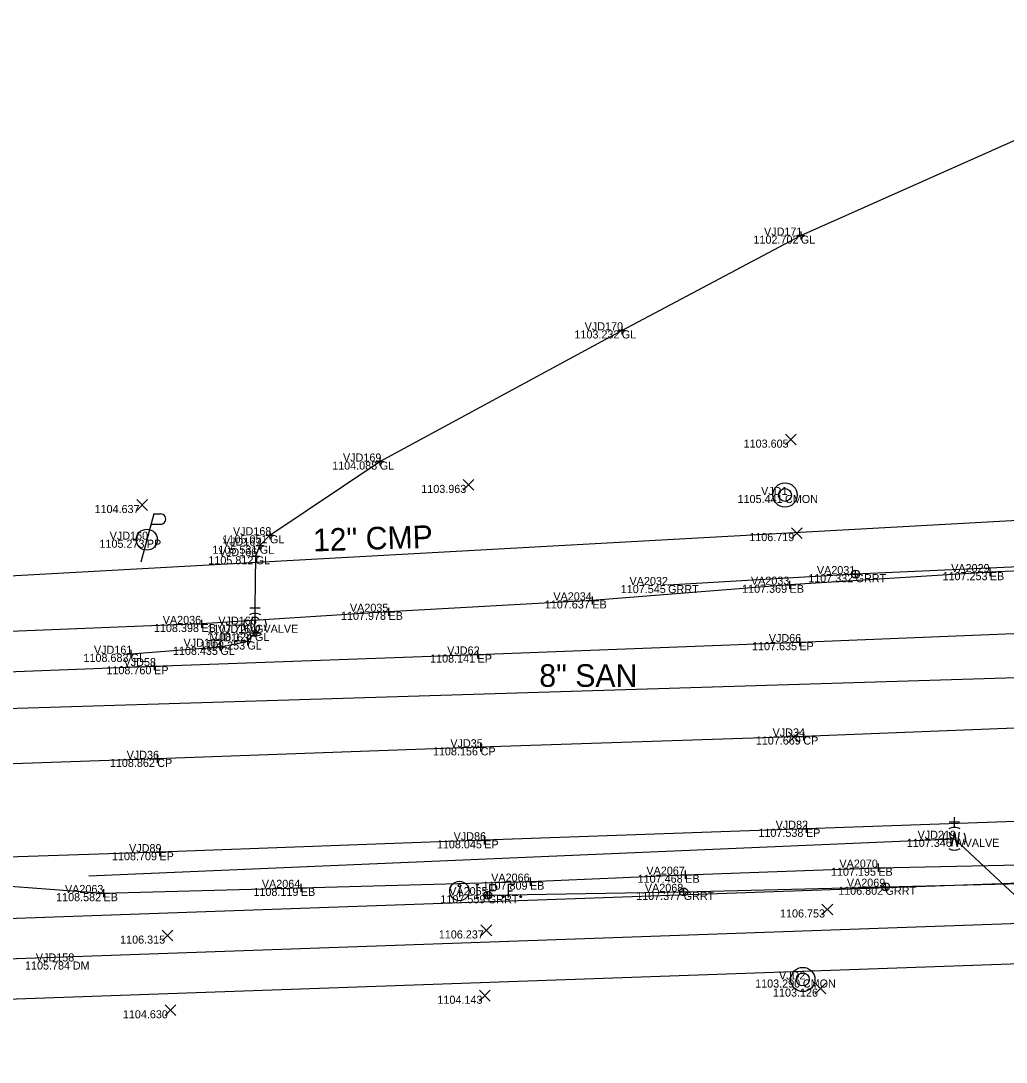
# Model space of a CAD drawing. Extents: x 1629915 to 1630675, y 484401 to 484601.
# Drawn here: x 1630085 to 1630207, y 484445.6 to 484574.6 of the extents above; entities that cross this region are included whole.
import ezdxf

# ---------------------------------------------------------------- set-up
doc = ezdxf.new("R2010")
doc.units = 0
for name, color, linetype in [('BR_X_Sub_Foot_Object', 7, 'Continuous'), ('Default', 7, 'Continuous'), ('DR_X_Storm_Sewer', 7, 'Continuous'), ('PV_X_COP', 7, 'Continuous'), ('PV_X_EOP', 7, 'Continuous'), ('PV_X_Shoulder_Aggregate', 7, 'Continuous'), ('RD_X_GR_Rt', 7, 'Continuous'), ('SC_Scratch2', 7, 'Continuous'), ('SV_X_Mon_Cells_Found', 7, 'Continuous'), ('SV_X_Random_Point', 7, 'Continuous'), ('SV_X_Shot_Marker', 7, 'Continuous'), ('SV_X_Text_Comment', 7, 'Continuous'), ('SV_X_Text_Elevation', 7, 'Continuous'), ('SV_X_Text_Name', 7, 'Continuous'), ('TX_X_20', 7, 'Continuous'), ('UT_X_Electric_Cells', 7, 'Continuous'), ('UT_X_Gas', 7, 'Continuous'), ('UT_X_Gas_Cells', 7, 'Continuous'), ('UT_X_Sanitary_Line', 7, 'Continuous'), ('UT_X_Water', 7, 'Continuous'), ('UT_X_Water_Cells', 7, 'Continuous')]:
    doc.layers.add(name, color=color, linetype=linetype)

# ---------------------------------------------------------------- blocks, each defined once
blk = doc.blocks.new('SurveyPointCell')
at = {"layer": 'Default'}
for p, q in [((-0.5, 0), (0.5, 0)), ((0, -0.5), (0, 0.5))]:
    blk.add_line(p, q, dxfattribs=at)
blk.add_circle((0, 0), 0.5, dxfattribs=at)

msp = doc.modelspace()

# ---------------------------------------------------------------- linework, layer by layer
at = {"layer": 'BR_X_Sub_Foot_Object'}
for p, q in [((1629921.46, 484457.7), (1630334.81, 484472.22)), ((1629921.64, 484452.7), (1630334.98, 484467.23)), ((1629921.81, 484447.71), (1630335.16, 484462.23))]:
    msp.add_line(p, q, dxfattribs=at)
at = {"layer": 'DR_X_Storm_Sewer'}
msp.add_line((1630034.14, 484503.09), (1630277.8, 484516.55), dxfattribs=at)
at = {"layer": 'PV_X_COP'}
msp.add_lwpolyline([(1630268.33, 484489.25), (1630243.24, 484488.19), (1630219.61, 484487.4), (1630181.89, 484485.93), (1630141.91, 484484.59), (1630101.85, 484483.16), (1630058.97, 484481.67), (1630018.45, 484480.34), (1629978.04, 484478.79), (1629939.2, 484477.21)], dxfattribs=at)
at = {"layer": 'PV_X_EOP'}
for points in [[(1629938.79, 484488.62), (1629977.75, 484490.2), (1630018.11, 484491.66), (1630058.6, 484492.97), (1630101.46, 484494.64), (1630141.53, 484496.09), (1630181.4, 484497.62), (1630219.2, 484499.13), (1630242.8, 484500), (1630272.75, 484501.05)], [(1630263.78, 484477.41), (1630243.53, 484476.68), (1630220, 484475.82), (1630182.22, 484474.5), (1630142.36, 484473.07), (1630102.12, 484471.6), (1630059.53, 484470.19), (1630018.19, 484468.84), (1629978.31, 484467.43), (1629939.56, 484465.91)]]:
    msp.add_lwpolyline(points, dxfattribs=at)
at = {"layer": 'PV_X_Shoulder_Aggregate'}
for points in [[(1630275.86, 484507.82), (1630275.94, 484508.43), (1630251.77, 484507.98), (1630226.06, 484507.18), (1630204.99, 484506.29), (1630180.18, 484504.73), (1630155.75, 484502.79), (1630130.5, 484501.38), (1630107.34, 484499.87), (1630082.61, 484498.88), (1630057.42, 484497.85), (1630056.68, 484498.18), (1630055.97, 484498.79), (1630036.74, 484497.12), (1630036.52, 484496.78), (1630005.44, 484493), (1629981.15, 484491.33), (1629968.09, 484490.84), (1629967.17, 484490.75), (1629965.31, 484491.8), (1629947.85, 484491.52), (1629935.77, 484490.2), (1629921.04, 484489.43)], [(1629924.92, 484463.1), (1629930.05, 484463.83), (1629958.35, 484464.98), (1629985.48, 484465.94), (1629989.88, 484465.79), (1629994.28, 484464.53), (1629995.64, 484464.34), (1630011.36, 484464.74), (1630016.57, 484465.2), (1630018.98, 484466.33), (1630028.74, 484467.4), (1630055.54, 484468.29), (1630066.15, 484468.61), (1630075.38, 484468), (1630095.19, 484466.53), (1630119.64, 484467.18), (1630148.03, 484467.95), (1630167.26, 484468.81), (1630191.18, 484469.68), (1630216.42, 484470.19), (1630228.43, 484470.02), (1630254.62, 484470.78), (1630261.49, 484471.01)]]:
    msp.add_lwpolyline(points, dxfattribs=at)
at = {"layer": 'RD_X_GR_Rt'}
for points in [[(1630276.94, 484509.76), (1630213.2, 484507.14), (1630188.36, 484506.04), (1630165.14, 484504.69)], [(1630142.8, 484466.27), (1630167.07, 484466.68), (1630192.07, 484467.32), (1630261.51, 484469.02)]]:
    msp.add_lwpolyline(points, dxfattribs=at)
at = {"layer": 'SC_Scratch2'}
for p, q in [((1630165.12, 484504.69), (1630165.17, 484504.69)), ((1630165.14, 484504.72), (1630165.14, 484504.67)), ((1630165.14, 484504.69), (1630165.14, 484504.69))]:
    msp.add_line(p, q, dxfattribs=at)
at = {"layer": 'SV_X_Mon_Cells_Found'}
msp.add_line((1630139.29, 484466.91), (1630139.29, 484466.03), dxfattribs=at)
for points in [[(1630141.32, 484467.59), (1630141.67, 484467.59)], [(1630141.49, 484465.99), (1630141.49, 484467.59)], [(1630143.06, 484465.99), (1630143.06, 484467.59), (1630143.59, 484467.59), (1630143.64, 484467.58), (1630143.72, 484467.56), (1630143.75, 484467.53), (1630143.79, 484467.51), (1630143.83, 484467.44), (1630143.86, 484467.38), (1630143.88, 484467.28), (1630143.88, 484467.13), (1630143.87, 484467.08), (1630143.85, 484467), (1630143.81, 484466.91), (1630143.76, 484466.88), (1630143.73, 484466.85), (1630143.67, 484466.82), (1630143.59, 484466.81), (1630143.06, 484466.81)], [(1630146.07, 484467.59), (1630145.31, 484467.59), (1630145.31, 484465.99)], [(1630145.31, 484466.81), (1630145.85, 484466.81)], [(1630141.32, 484465.99), (1630141.67, 484465.99)], [(1630142.45, 484466.21), (1630142.51, 484466.21), (1630142.54, 484466.18), (1630142.57, 484466.13), (1630142.57, 484466.07), (1630142.54, 484466.02), (1630142.51, 484465.99), (1630142.45, 484465.99), (1630142.42, 484466.02), (1630142.39, 484466.07), (1630142.39, 484466.13), (1630142.42, 484466.18), (1630142.45, 484466.21)], [(1630144.7, 484466.21), (1630144.76, 484466.21), (1630144.79, 484466.18), (1630144.82, 484466.13), (1630144.82, 484466.07), (1630144.79, 484466.02), (1630144.76, 484465.99), (1630144.7, 484465.99), (1630144.67, 484466.02), (1630144.63, 484466.07), (1630144.63, 484466.13), (1630144.67, 484466.18), (1630144.7, 484466.21)], [(1630146.85, 484466.21), (1630146.9, 484466.21), (1630146.94, 484466.18), (1630146.97, 484466.13), (1630146.97, 484466.07), (1630146.94, 484466.02), (1630146.9, 484465.99), (1630146.85, 484465.99), (1630146.82, 484466.02), (1630146.78, 484466.07), (1630146.78, 484466.13), (1630146.82, 484466.18), (1630146.85, 484466.21)]]:
    msp.add_lwpolyline(points, dxfattribs=at)
for centre, radius in [((1630179.62, 484515.85), 1.5), ((1630179.62, 484515.85), 0.8), ((1630139.29, 484466.79), 1.2), ((1630139.29, 484467.45), 0.16), ((1630181.83, 484455.83), 1.5), ((1630181.83, 484455.83), 0.8)]:
    msp.add_circle(centre, radius, dxfattribs=at)
at = {"layer": 'SV_X_Random_Point'}
for p, q in [((1630179.69, 484522.05), (1630181.02, 484523.38)), ((1630179.69, 484523.38), (1630181.02, 484522.05)), ((1630139.76, 484516.43), (1630141.09, 484517.77)), ((1630139.76, 484517.77), (1630141.09, 484516.43)), ((1630099.31, 484513.94), (1630100.64, 484515.28)), ((1630099.31, 484515.28), (1630100.64, 484513.94)), ((1630180.41, 484510.46), (1630181.74, 484511.79)), ((1630180.41, 484511.79), (1630181.74, 484510.46)), ((1630180.06, 484485.17), (1630181.4, 484486.51)), ((1630180.06, 484486.51), (1630181.4, 484485.17)), ((1630184.19, 484463.85), (1630185.53, 484465.18)), ((1630184.19, 484465.18), (1630185.53, 484463.85)), ((1630141.95, 484461.24), (1630143.29, 484462.58)), ((1630141.95, 484462.58), (1630143.29, 484461.24)), ((1630102.45, 484460.6), (1630103.78, 484461.93)), ((1630102.45, 484461.93), (1630103.78, 484460.6)), ((1630183.36, 484454.04), (1630184.69, 484455.38)), ((1630183.36, 484455.38), (1630184.69, 484454.04)), ((1630141.76, 484453.15), (1630143.09, 484454.49)), ((1630141.76, 484454.49), (1630143.09, 484453.15)), ((1630102.83, 484451.35), (1630104.17, 484452.68)), ((1630102.83, 484452.68), (1630104.17, 484451.35))]:
    msp.add_line(p, q, dxfattribs=at)
at = {"layer": 'SV_X_Shot_Marker'}
for p, q in [((1630181.08, 484547.98), (1630182.08, 484547.98)), ((1630181.58, 484548.48), (1630181.58, 484547.48)), ((1630181.58, 484547.98), (1630181.58, 484547.98)), ((1630158.9, 484536.24), (1630159.9, 484536.24)), ((1630159.4, 484536.74), (1630159.4, 484535.74)), ((1630159.4, 484536.24), (1630159.4, 484536.24)), ((1630128.92, 484519.99), (1630129.92, 484519.99)), ((1630129.42, 484520.49), (1630129.42, 484519.49)), ((1630129.42, 484519.99), (1630129.42, 484519.99)), ((1630115.31, 484510.86), (1630116.31, 484510.86)), ((1630115.81, 484511.36), (1630115.81, 484510.36)), ((1630115.81, 484510.86), (1630115.81, 484510.86)), ((1630114.06, 484509.57), (1630115.06, 484509.57)), ((1630114.56, 484510.07), (1630114.56, 484509.07)), ((1630114.56, 484509.57), (1630114.56, 484509.57)), ((1630113.55, 484508.26), (1630114.55, 484508.26)), ((1630114.05, 484508.76), (1630114.05, 484507.76)), ((1630114.05, 484508.26), (1630114.05, 484508.26)), ((1630204.99, 484506.79), (1630204.99, 484505.79)), ((1630180.18, 484505.23), (1630180.18, 484504.23)), ((1630204.49, 484506.29), (1630205.49, 484506.29)), ((1630204.99, 484506.29), (1630204.99, 484506.29)), ((1630179.68, 484504.73), (1630180.68, 484504.73)), ((1630180.18, 484504.73), (1630180.18, 484504.73)), ((1630155.25, 484502.79), (1630156.25, 484502.79)), ((1630155.75, 484503.29), (1630155.75, 484502.29)), ((1630155.75, 484502.79), (1630155.75, 484502.79)), ((1630130, 484501.38), (1630131, 484501.38)), ((1630130.5, 484501.88), (1630130.5, 484500.88)), ((1630130.5, 484501.38), (1630130.5, 484501.38)), ((1630107.34, 484500.37), (1630107.34, 484499.37)), ((1630106.84, 484499.87), (1630107.84, 484499.87)), ((1630107.34, 484499.87), (1630107.34, 484499.87)), ((1630113.45, 484498.76), (1630114.45, 484498.76)), ((1630113.95, 484499.26), (1630113.95, 484498.26)), ((1630113.95, 484498.76), (1630113.95, 484498.76)), ((1630109.66, 484497.54), (1630109.66, 484496.54)), ((1630112.52, 484497.7), (1630113.52, 484497.7)), ((1630113.02, 484498.2), (1630113.02, 484497.2)), ((1630113.02, 484497.7), (1630113.02, 484497.7)), ((1630180.9, 484497.62), (1630181.9, 484497.62)), ((1630181.4, 484498.12), (1630181.4, 484497.12)), ((1630181.4, 484497.62), (1630181.4, 484497.62)), ((1630098.07, 484496.17), (1630099.07, 484496.17)), ((1630098.57, 484496.67), (1630098.57, 484495.67)), ((1630098.57, 484496.17), (1630098.57, 484496.17)), ((1630109.16, 484497.04), (1630110.16, 484497.04)), ((1630109.66, 484497.04), (1630109.66, 484497.04)), ((1630141.03, 484496.09), (1630142.03, 484496.09)), ((1630141.53, 484496.59), (1630141.53, 484495.59)), ((1630141.53, 484496.09), (1630141.53, 484496.09)), ((1630101.46, 484495.14), (1630101.46, 484494.14)), ((1630100.96, 484494.64), (1630101.96, 484494.64)), ((1630101.46, 484494.64), (1630101.46, 484494.64)), ((1630181.39, 484485.93), (1630182.39, 484485.93)), ((1630181.89, 484486.43), (1630181.89, 484485.43)), ((1630181.89, 484485.93), (1630181.89, 484485.93)), ((1630141.41, 484484.59), (1630142.41, 484484.59)), ((1630141.91, 484485.09), (1630141.91, 484484.09)), ((1630141.91, 484484.59), (1630141.91, 484484.59)), ((1630101.35, 484483.16), (1630102.35, 484483.16)), ((1630101.85, 484483.66), (1630101.85, 484482.66)), ((1630101.85, 484483.16), (1630101.85, 484483.16)), ((1630181.72, 484474.5), (1630182.72, 484474.5)), ((1630182.22, 484475), (1630182.22, 484474)), ((1630182.22, 484474.5), (1630182.22, 484474.5)), ((1630141.86, 484473.07), (1630142.86, 484473.07)), ((1630142.36, 484473.57), (1630142.36, 484472.57)), ((1630142.36, 484473.07), (1630142.36, 484473.07)), ((1630101.62, 484471.6), (1630102.62, 484471.6)), ((1630102.12, 484472.1), (1630102.12, 484471.1)), ((1630102.12, 484471.6), (1630102.12, 484471.6)), ((1630167.26, 484469.31), (1630167.26, 484468.31)), ((1630190.68, 484469.68), (1630191.68, 484469.68)), ((1630191.18, 484470.18), (1630191.18, 484469.18)), ((1630191.18, 484469.68), (1630191.18, 484469.68)), ((1630119.64, 484467.68), (1630119.64, 484466.68)), ((1630147.53, 484467.95), (1630148.53, 484467.95)), ((1630148.03, 484468.45), (1630148.03, 484467.45)), ((1630148.03, 484467.95), (1630148.03, 484467.95)), ((1630166.76, 484468.81), (1630167.76, 484468.81)), ((1630167.26, 484468.81), (1630167.26, 484468.81)), ((1630094.69, 484466.53), (1630095.69, 484466.53)), ((1630095.19, 484467.03), (1630095.19, 484466.03)), ((1630095.19, 484466.53), (1630095.19, 484466.53)), ((1630119.14, 484467.18), (1630120.14, 484467.18)), ((1630119.64, 484467.18), (1630119.64, 484467.18))]:
    msp.add_line(p, q, dxfattribs=at)
at = {"layer": 'UT_X_Electric_Cells'}
for p, q in [((1630101.41, 484513.51), (1630099.81, 484507.51)), ((1630101.41, 484513.51), (1630102.26, 484513.51)), ((1630101.07, 484512.23), (1630102.26, 484512.23))]:
    msp.add_line(p, q, dxfattribs=at)
msp.add_circle((1630100.56, 484510.31), 1.3, dxfattribs=at)
msp.add_arc((1630102.27, 484512.87), 0.638, 268.8767, 91.1233, dxfattribs=at)
at = {"layer": 'UT_X_Gas'}
for points in [[(1630098.57, 484496.17), (1630109.66, 484497.04), (1630113.02, 484497.7), (1630113.95, 484498.76), (1630114.05, 484508.26), (1630114.56, 484509.57), (1630115.81, 484510.86), (1630129.42, 484519.99), (1630159.4, 484536.24), (1630181.58, 484547.98), (1630213.12, 484562.01), (1630240.48, 484573.33), (1630274.59, 484574.58), (1630290.01, 484572.98), (1630327.07, 484564.38), (1630366.66, 484567.36), (1630393.12, 484565.9), (1630419.95, 484549.24), (1630440.64, 484526.36), (1630450.49, 484510.25), (1630452.08, 484508.49), (1630453.28, 484508.55), (1630468.94, 484509.13)], [(1630098.57, 484496.17), (1630109.66, 484497.04), (1630113.02, 484497.7), (1630113.95, 484498.76), (1630114.05, 484508.26), (1630114.56, 484509.57), (1630115.81, 484510.86), (1630129.42, 484519.99), (1630159.4, 484536.24), (1630181.58, 484547.98), (1630213.12, 484562.01), (1630240.48, 484573.33), (1630274.59, 484574.58), (1630290.01, 484572.98), (1630327.07, 484564.38), (1630366.66, 484567.36), (1630393.12, 484565.9), (1630419.95, 484549.24), (1630440.64, 484526.36), (1630450.49, 484510.25), (1630452.08, 484508.49), (1630453.28, 484508.55), (1630494.38, 484510.08)]]:
    msp.add_lwpolyline(points, dxfattribs=at)
at = {"layer": 'UT_X_Gas_Cells'}
for p, q in [((1630114.6, 484501.81), (1630113.33, 484501.81)), ((1630113.97, 484501.18), (1630113.97, 484502.45)), ((1630113.97, 484499.78), (1630113.97, 484499.78))]:
    msp.add_line(p, q, dxfattribs=at)
msp.add_lwpolyline([(1630114.5, 484500.32), (1630114.49, 484500.4), (1630114.44, 484500.47), (1630114.37, 484500.54), (1630114.27, 484500.62), (1630114.2, 484500.65), (1630114.15, 484500.66), (1630114.06, 484500.68), (1630113.89, 484500.68), (1630113.82, 484500.66), (1630113.78, 484500.65), (1630113.72, 484500.62), (1630113.61, 484500.54), (1630113.54, 484500.44), (1630113.49, 484500.32), (1630113.47, 484500.17), (1630113.44, 484499.94), (1630113.44, 484499.64), (1630113.45, 484499.4), (1630113.51, 484499.22), (1630113.59, 484499.05), (1630113.66, 484498.99), (1630113.75, 484498.94), (1630113.9, 484498.88), (1630114.06, 484498.88), (1630114.22, 484498.91), (1630114.27, 484498.94), (1630114.33, 484498.96), (1630114.39, 484499.02), (1630114.44, 484499.11), (1630114.5, 484499.23), (1630114.5, 484499.59), (1630114.2, 484499.59)], dxfattribs=at)
for start, end in [(60.0184, 120.0157), (150.0184, 209.9816), (330.0184, 29.9816), (239.9843, 299.9816)]:
    msp.add_arc((1630113.97, 484499.78), 1.4, start, end, dxfattribs=at)
at = {"layer": 'UT_X_Sanitary_Line'}
msp.add_lwpolyline([(1629930.75, 484483.73), (1630048.13, 484488.31), (1630252.72, 484494.6), (1630261.76, 484567.79), (1630373.42, 484500.09), (1630654.86, 484509.35)], dxfattribs=at)
at = {"layer": 'UT_X_Water'}
for p, q in [((1630093.36, 484468.69), (1630200.61, 484473.26)), ((1630200.61, 484473.26), (1630230.15, 484445.59))]:
    msp.add_line(p, q, dxfattribs=at)
at = {"layer": 'UT_X_Water_Cells'}
for p, q in [((1630200.61, 484474.66), (1630200.61, 484475.93)), ((1630201.24, 484475.3), (1630199.97, 484475.3)), ((1630200.61, 484473.26), (1630200.61, 484473.26))]:
    msp.add_line(p, q, dxfattribs=at)
msp.add_lwpolyline([(1630199.97, 484474.08), (1630200.29, 484472.36), (1630200.61, 484474.08), (1630200.93, 484472.36), (1630201.24, 484474.08)], dxfattribs=at)
for start, end in [(60.0184, 120.0157), (150.0184, 209.9816), (330.0184, 29.9816), (239.9843, 299.9816)]:
    msp.add_arc((1630200.6, 484473.26), 1.4, start, end, dxfattribs=at)

# ---------------------------------------------------------------- block references
at = {"layer": 'SC_Scratch2'}
for p in [(1630188.36, 484506.04), (1630192.07, 484467.32), (1630142.8, 484466.27), (1630167.07, 484466.68)]:
    msp.add_blockref('SurveyPointCell', p, dxfattribs=at)

# ---------------------------------------------------------------- texts
at = {"layer": 'SV_X_Text_Comment'}
for s, p in [('GL', (1630181.58, 484546.98)), ('GL', (1630159.4, 484535.24)), ('GL', (1630129.42, 484518.99)), ('CMON', (1630179.62, 484514.85)), ('PP', (1630100.56, 484509.31)), ('GL', (1630115.81, 484509.86)), ('GL', (1630114.56, 484508.57)), ('GL', (1630114.05, 484507.26)), ('GRRT', (1630188.36, 484505.04)), ('EB', (1630204.99, 484505.29)), ('GRRT', (1630165.14, 484503.69)), ('EB', (1630180.18, 484503.73)), ('EB', (1630155.75, 484501.79)), ('EB', (1630130.5, 484500.38)), ('EB', (1630107.34, 484498.87)), ('GL', (1630113.95, 484497.76)), ('GVALVE', (1630113.97, 484498.78)), ('GL', (1630113.02, 484496.7)), ('EP', (1630181.4, 484496.62)), ('GL', (1630098.57, 484495.17)), ('GL', (1630109.66, 484496.04)), ('EP', (1630141.53, 484495.09)), ('EP', (1630101.46, 484493.64)), ('CP', (1630181.89, 484484.93)), ('CP', (1630141.91, 484483.59)), ('CP', (1630101.85, 484482.16)), ('EP', (1630182.22, 484473.5)), ('EP', (1630142.36, 484472.07)), ('WVALVE', (1630200.61, 484472.26)), ('EP', (1630102.12, 484470.6)), ('EB', (1630191.18, 484468.68)), ('EB', (1630148.03, 484466.95)), ('EB', (1630167.26, 484467.81)), ('EB', (1630095.19, 484465.53)), ('EB', (1630119.64, 484466.18)), ('GRRT', (1630167.07, 484465.68)), ('GRRT', (1630192.07, 484466.32)), ('GRRT', (1630142.8, 484465.27)), ('DM', (1630091.39, 484457.06)), ('CMON', (1630181.83, 484454.83))]:
    msp.add_text(s, height=1, dxfattribs=at).set_placement(p)
at = {"layer": 'SV_X_Text_Elevation'}
for s, p in [('1102.702', (1630175.71, 484546.98)), ('1103.232', (1630153.53, 484535.24)), ('1103.605', (1630174.49, 484521.71)), ('1104.088', (1630123.52, 484518.99)), ('1103.963', (1630134.56, 484516.1)), ('1105.441', (1630173.74, 484514.85)), ('1104.637', (1630094.08, 484513.61)), ('1105.273', (1630094.69, 484509.31)), ('1105.051', (1630109.93, 484509.86)), ('1106.719', (1630175.19, 484510.13)), ('1105.531', (1630108.68, 484508.57)), ('1105.812', (1630108.18, 484507.26)), ('1107.332', (1630182.49, 484505.04)), ('1107.253', (1630199.13, 484505.29)), ('1107.545', (1630159.27, 484503.69)), ('1107.369', (1630174.3, 484503.73)), ('1107.637', (1630149.86, 484501.79)), ('1107.978', (1630124.61, 484500.38)), ('1108.398', (1630101.44, 484498.87)), ('1108.124', (1630108.03, 484497.76)), ('1107.720', (1630108.06, 484498.78)), ('1108.253', (1630107.16, 484496.7)), ('1107.635', (1630175.53, 484496.62)), ('1108.683', (1630092.71, 484495.17)), ('1108.435', (1630103.79, 484496.04)), ('1108.141', (1630135.65, 484495.09)), ('1108.760', (1630095.55, 484493.64)), ('1107.669', (1630176, 484484.93)), ('1108.156', (1630136, 484483.59)), ('1108.862', (1630095.98, 484482.16)), ('1107.538', (1630176.32, 484473.5)), ('1108.045', (1630136.49, 484472.07)), ('1107.346', (1630194.7, 484472.26)), ('1108.709', (1630096.24, 484470.6)), ('1107.195', (1630185.31, 484468.68)), ('1107.809', (1630142.15, 484466.95)), ('1107.468', (1630161.36, 484467.81)), ('1108.582', (1630089.32, 484465.53)), ('1108.119', (1630113.76, 484466.18)), ('1107.377', (1630161.18, 484465.68)), ('1106.802', (1630186.2, 484466.32)), ('1107.559', (1630136.92, 484465.27)), ('1106.753', (1630179, 484463.51)), ('1106.315', (1630097.25, 484460.27)), ('1106.237', (1630136.73, 484460.91)), ('1105.784', (1630085.47, 484457.06)), ('1103.290', (1630175.92, 484454.83)), ('1104.143', (1630136.56, 484452.82)), ('1103.126', (1630178.13, 484453.71)), ('1104.630', (1630097.59, 484451.02))]:
    msp.add_text(s, height=1, dxfattribs=at).set_placement(p)
at = {"layer": 'SV_X_Text_Name'}
for s, p in [('VJD171', (1630177.02, 484547.98)), ('VJD170', (1630154.8, 484536.24)), ('VJD169', (1630124.86, 484519.99)), ('VJD1', (1630176.66, 484515.85)), ('VJD168', (1630111.23, 484510.86)), ('VJD160', (1630095.96, 484510.31)), ('VJD167', (1630109.98, 484509.57)), ('VJD166', (1630109.47, 484508.26)), ('VA2031', (1630183.57, 484506.04)), ('VA2029', (1630200.2, 484506.29)), ('VA2032', (1630160.36, 484504.69)), ('VA2033', (1630175.4, 484504.73)), ('VA2034', (1630150.92, 484502.79)), ('VA2035', (1630125.72, 484501.38)), ('VA2036', (1630102.53, 484499.87)), ('VJD165', (1630109.42, 484499.78)), ('VJD163', (1630108.47, 484497.7)), ('VJD164', (1630109.35, 484498.76)), ('VJD66', (1630177.61, 484497.62)), ('VJD162', (1630105.11, 484497.04)), ('VJD161', (1630094.01, 484496.17)), ('VJD62', (1630137.77, 484496.09)), ('VJD58', (1630097.68, 484494.64)), ('VJD34', (1630178.08, 484485.93)), ('VJD35', (1630138.16, 484484.59)), ('VJD36', (1630098.06, 484483.16)), ('VJD82', (1630178.46, 484474.5)), ('VJD86', (1630138.57, 484473.07)), ('VJD219', (1630196.04, 484473.26)), ('VJD89', (1630098.36, 484471.6)), ('VA2070', (1630186.36, 484469.68)), ('VA2066', (1630143.22, 484467.95)), ('VA2067', (1630162.45, 484468.81)), ('VA2064', (1630114.81, 484467.18)), ('VA2068', (1630162.26, 484466.68)), ('VA2069', (1630187.28, 484467.32)), ('VA2063', (1630090.42, 484466.53)), ('VA2065', (1630138.02, 484466.27)), ('VJD158', (1630086.81, 484458.06)), ('VJD2', (1630178.88, 484455.83))]:
    msp.add_text(s, height=1, dxfattribs=at).set_placement(p)
at = {"layer": 'TX_X_20'}
msp.add_text('12" CMP', height=2.8, rotation=1.7995, dxfattribs=at).set_placement((1630121.18, 484508.85))
msp.add_text('8" SAN', height=2.8, dxfattribs=at).set_placement((1630149.18, 484492.08))

doc.saveas('drawing.dxf')
